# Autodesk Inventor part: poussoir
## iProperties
Created: 2001-10
Part Number: poussoir
Material: Par défaut
Document SubType Name: Modélisation
Control State: 0
Master: False
Checked Out: False
Shininess: 21.0
Length Units: 11269
Angle Units: 11279
Time Units: 11290
Mass Units: 11283
Length Display Precision: 3
Angle Display Precision: 2
Density: 0.0
Volumn: 0.0
Area: 0.0
PropertySet Name: Model Information
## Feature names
1. Révolution1 [Revolution]
2. Perçage1 [Hole]
